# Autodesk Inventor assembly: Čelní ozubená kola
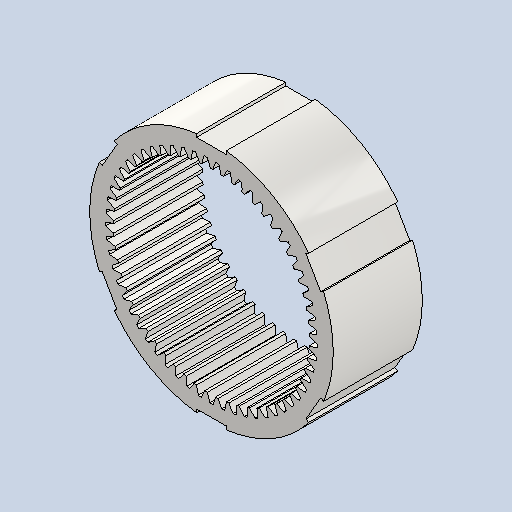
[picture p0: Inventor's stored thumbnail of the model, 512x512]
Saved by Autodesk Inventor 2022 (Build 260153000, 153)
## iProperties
ClientObjectVersion: 1
Created: 2025-05
Part Number: Čelní ozubená kola
Document SubType Name: Assembly
Designer: jbart
Categories: <?xml version="1.0" encoding="UTF-16"?> <MemberInstance><Categories><FamilyTemplate/><ParamToTemplateMap><ParamToTemplate><ParamToTemplate CategoryParameter="//
Author: jbart
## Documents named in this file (2)
- C:\Users\jbart\OneDrive\Dokumenty\Inventor\Převodovka navijáku\Korunové kolo 1\Design Accelerator\Čelní ozubená kola1.iam
- C:\Users\jbart\OneDrive\Dokumenty\Inventor\Převodovka navijáku\Korunové kolo 1\Design Accelerator\Čelní ozubené kolo21.ipt
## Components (1 placed, 1 different names)
1. Čelní ozubené kolo2:1
